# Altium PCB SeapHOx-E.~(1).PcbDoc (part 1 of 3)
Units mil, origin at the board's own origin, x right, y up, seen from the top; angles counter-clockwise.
Board outline 7300 x 3625 mil, 4 copper layers (Top Layer, Internal Plane 1, Signal Layer 1, Bottom Layer), stack 30.634 mil thick; 244 components, 217 nets, 966 pads, 416 vias.
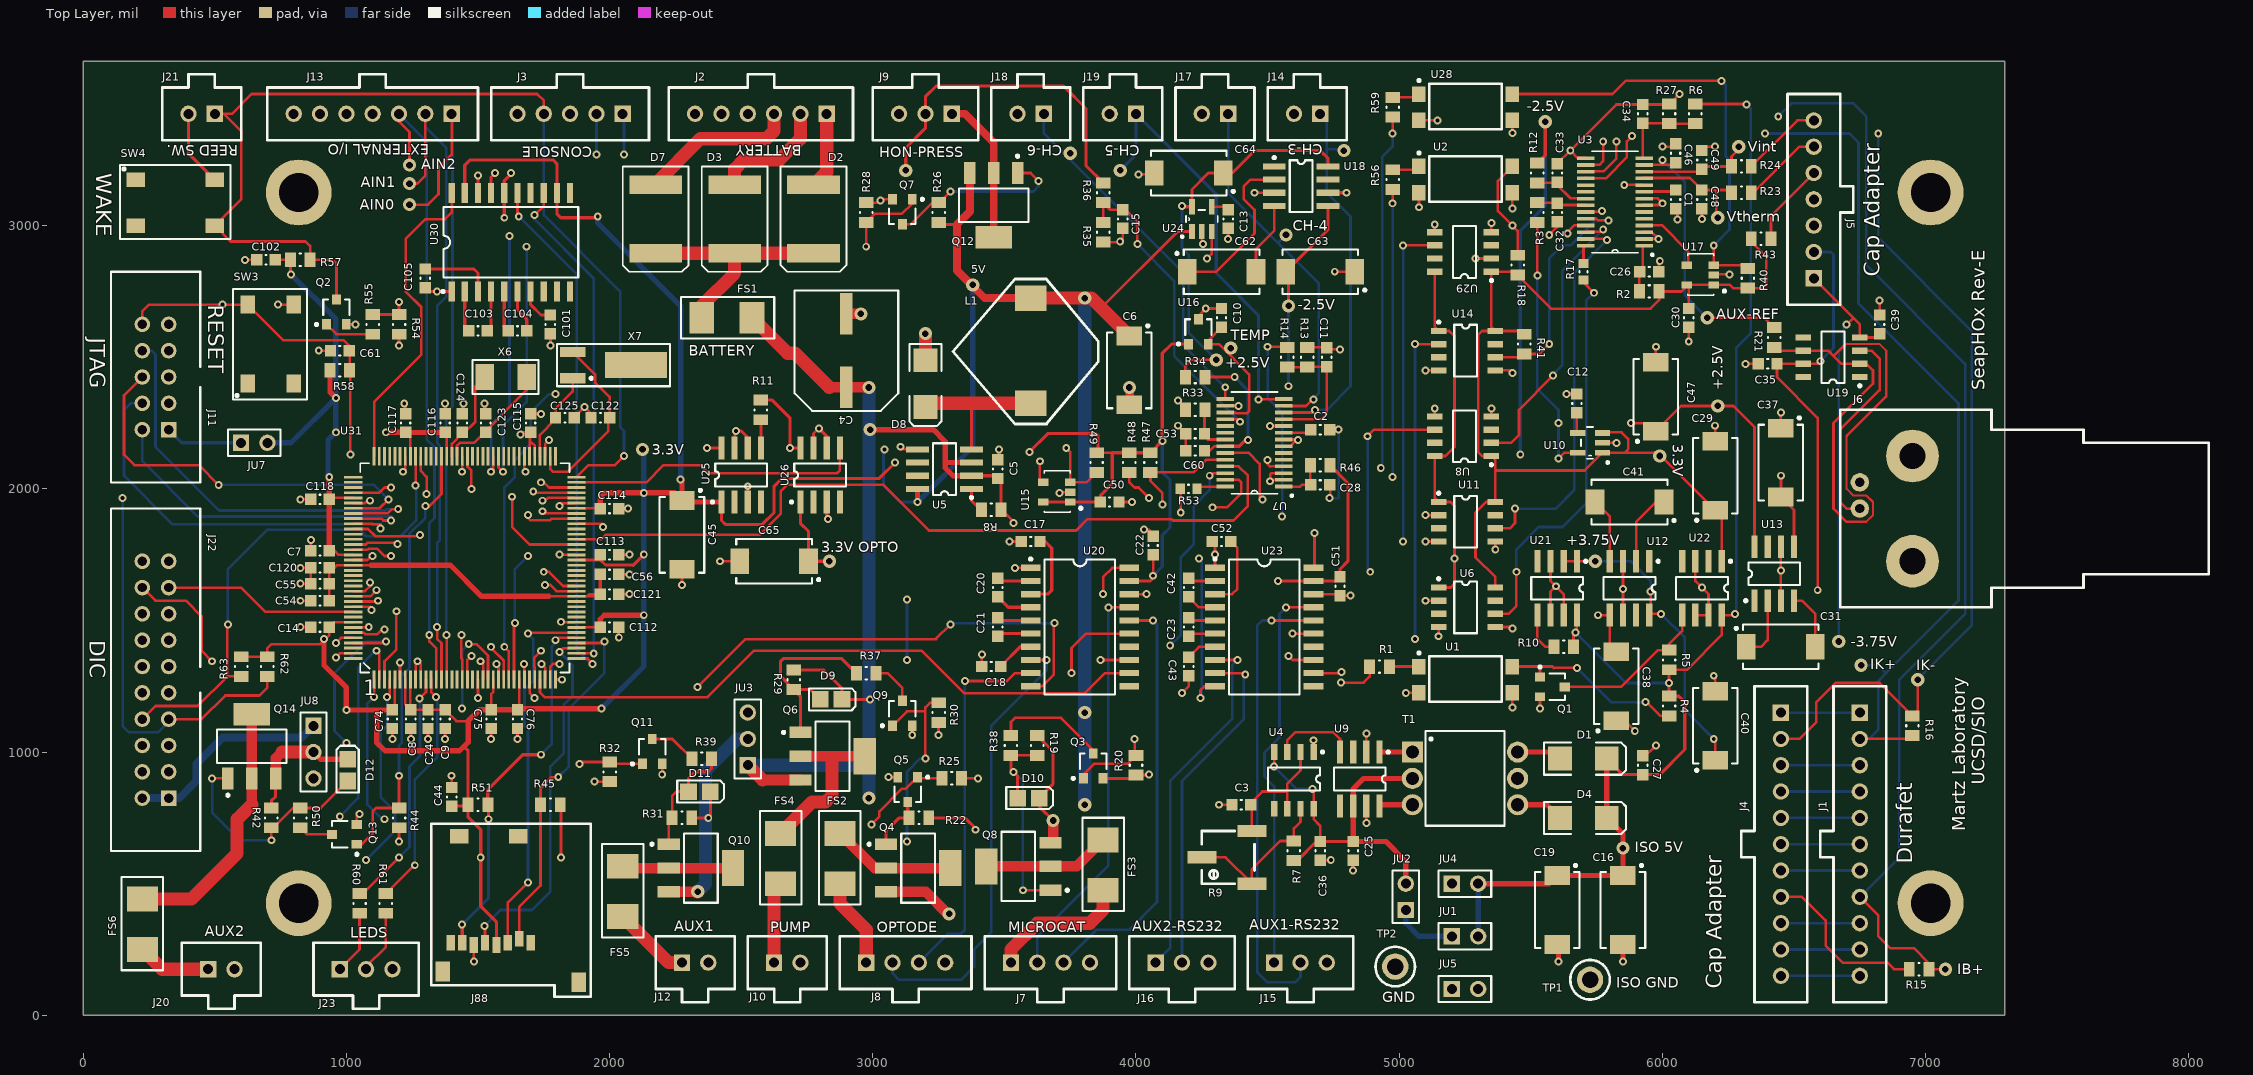
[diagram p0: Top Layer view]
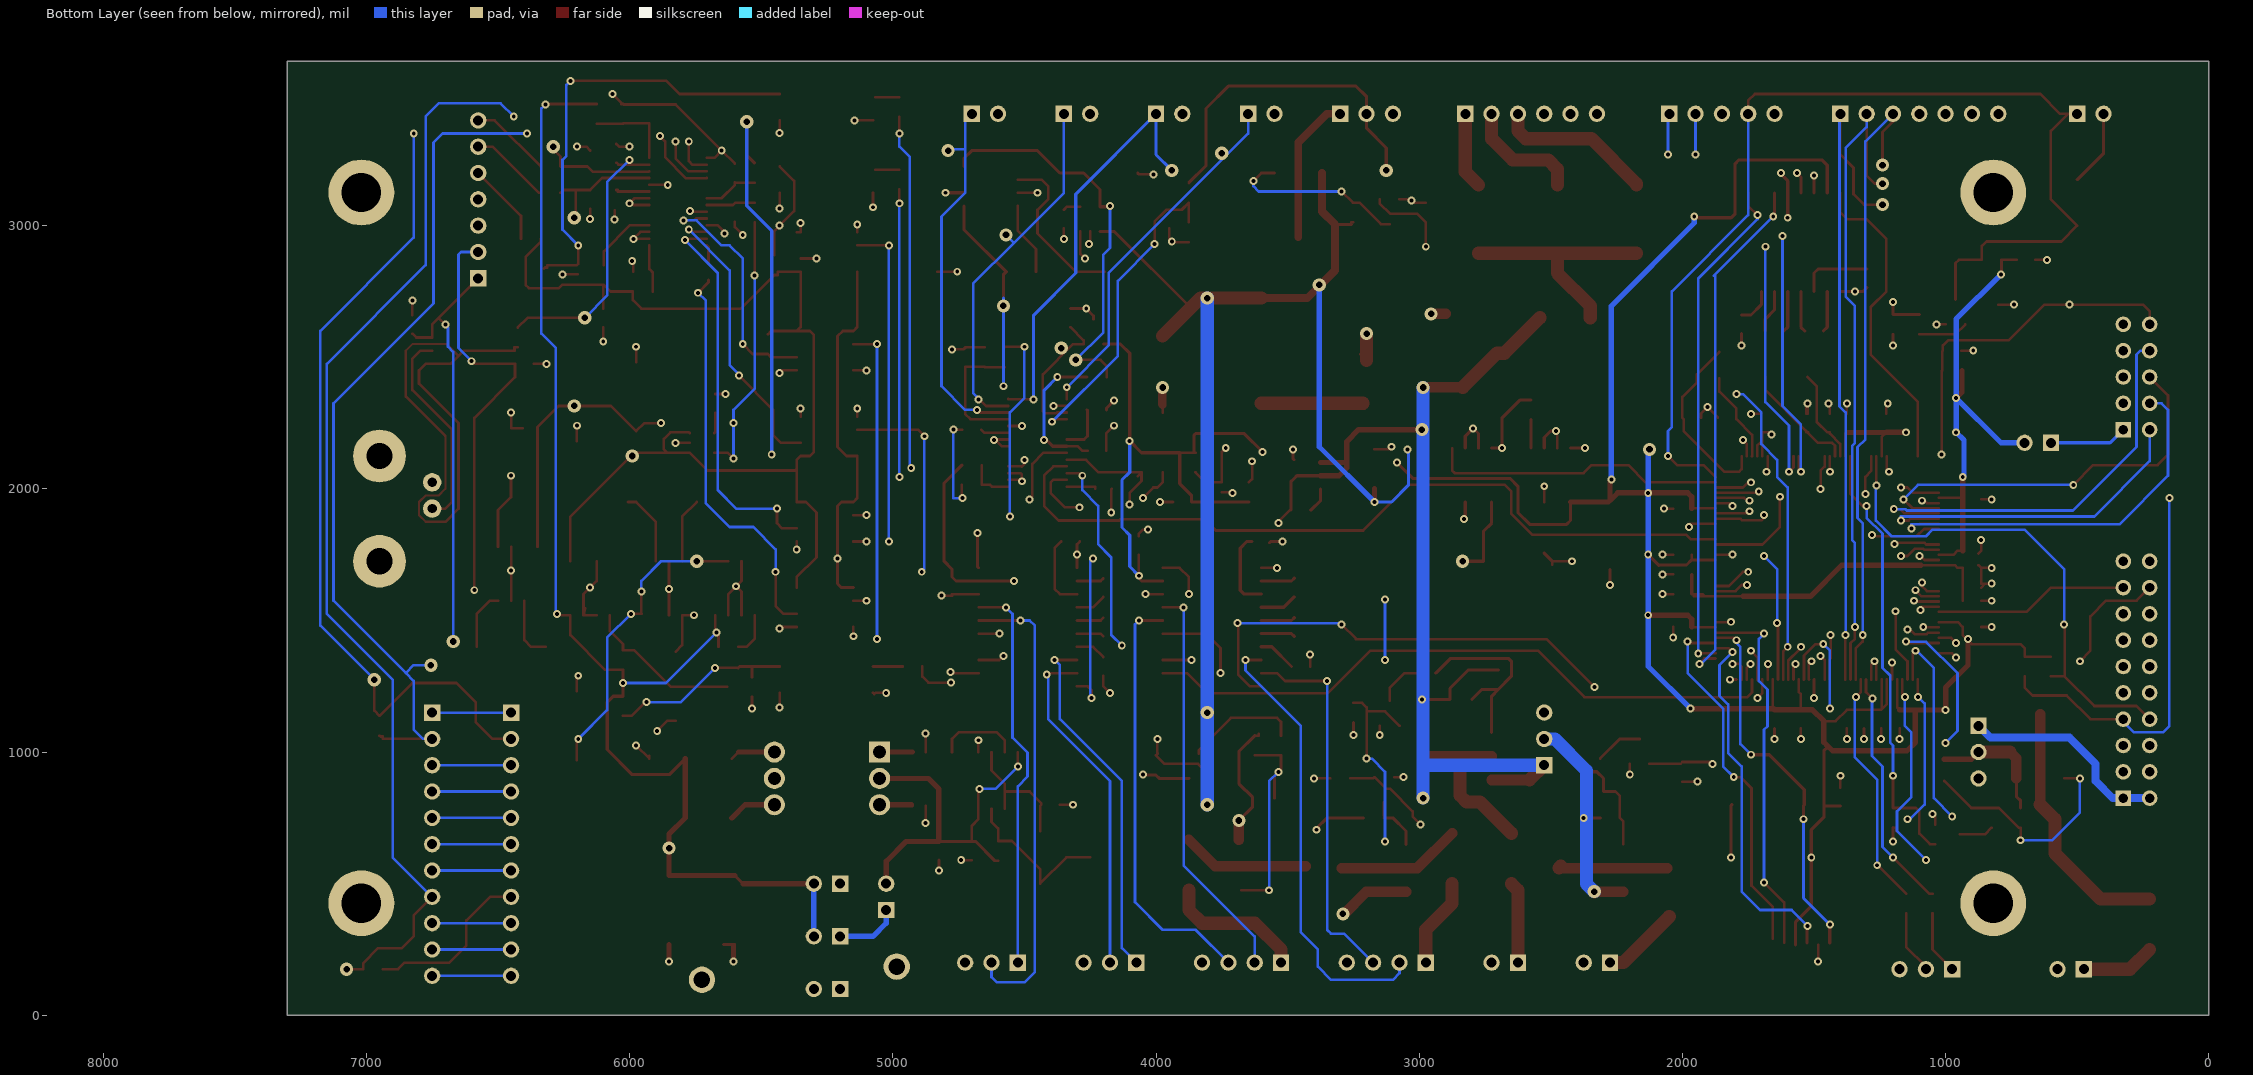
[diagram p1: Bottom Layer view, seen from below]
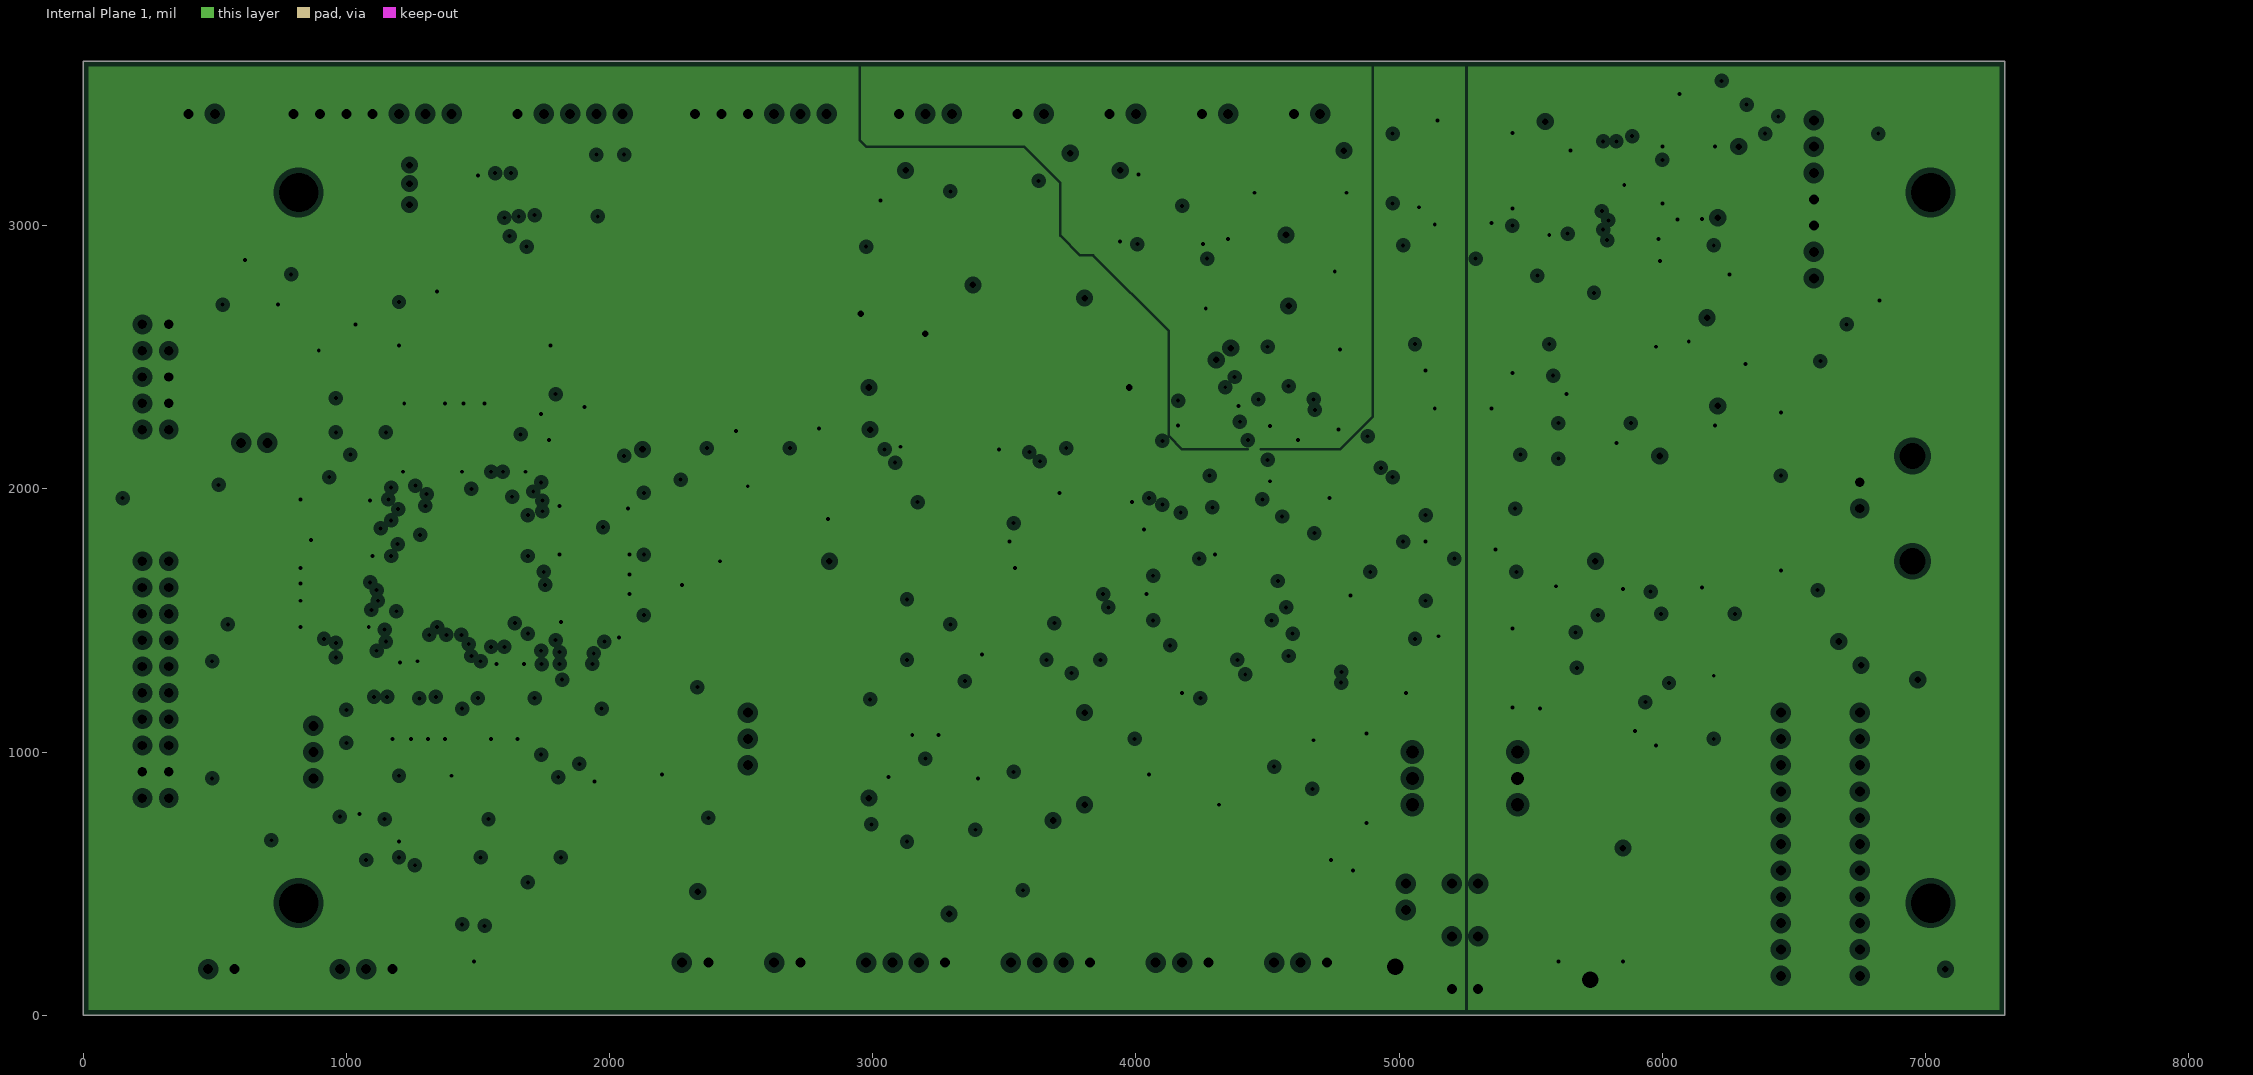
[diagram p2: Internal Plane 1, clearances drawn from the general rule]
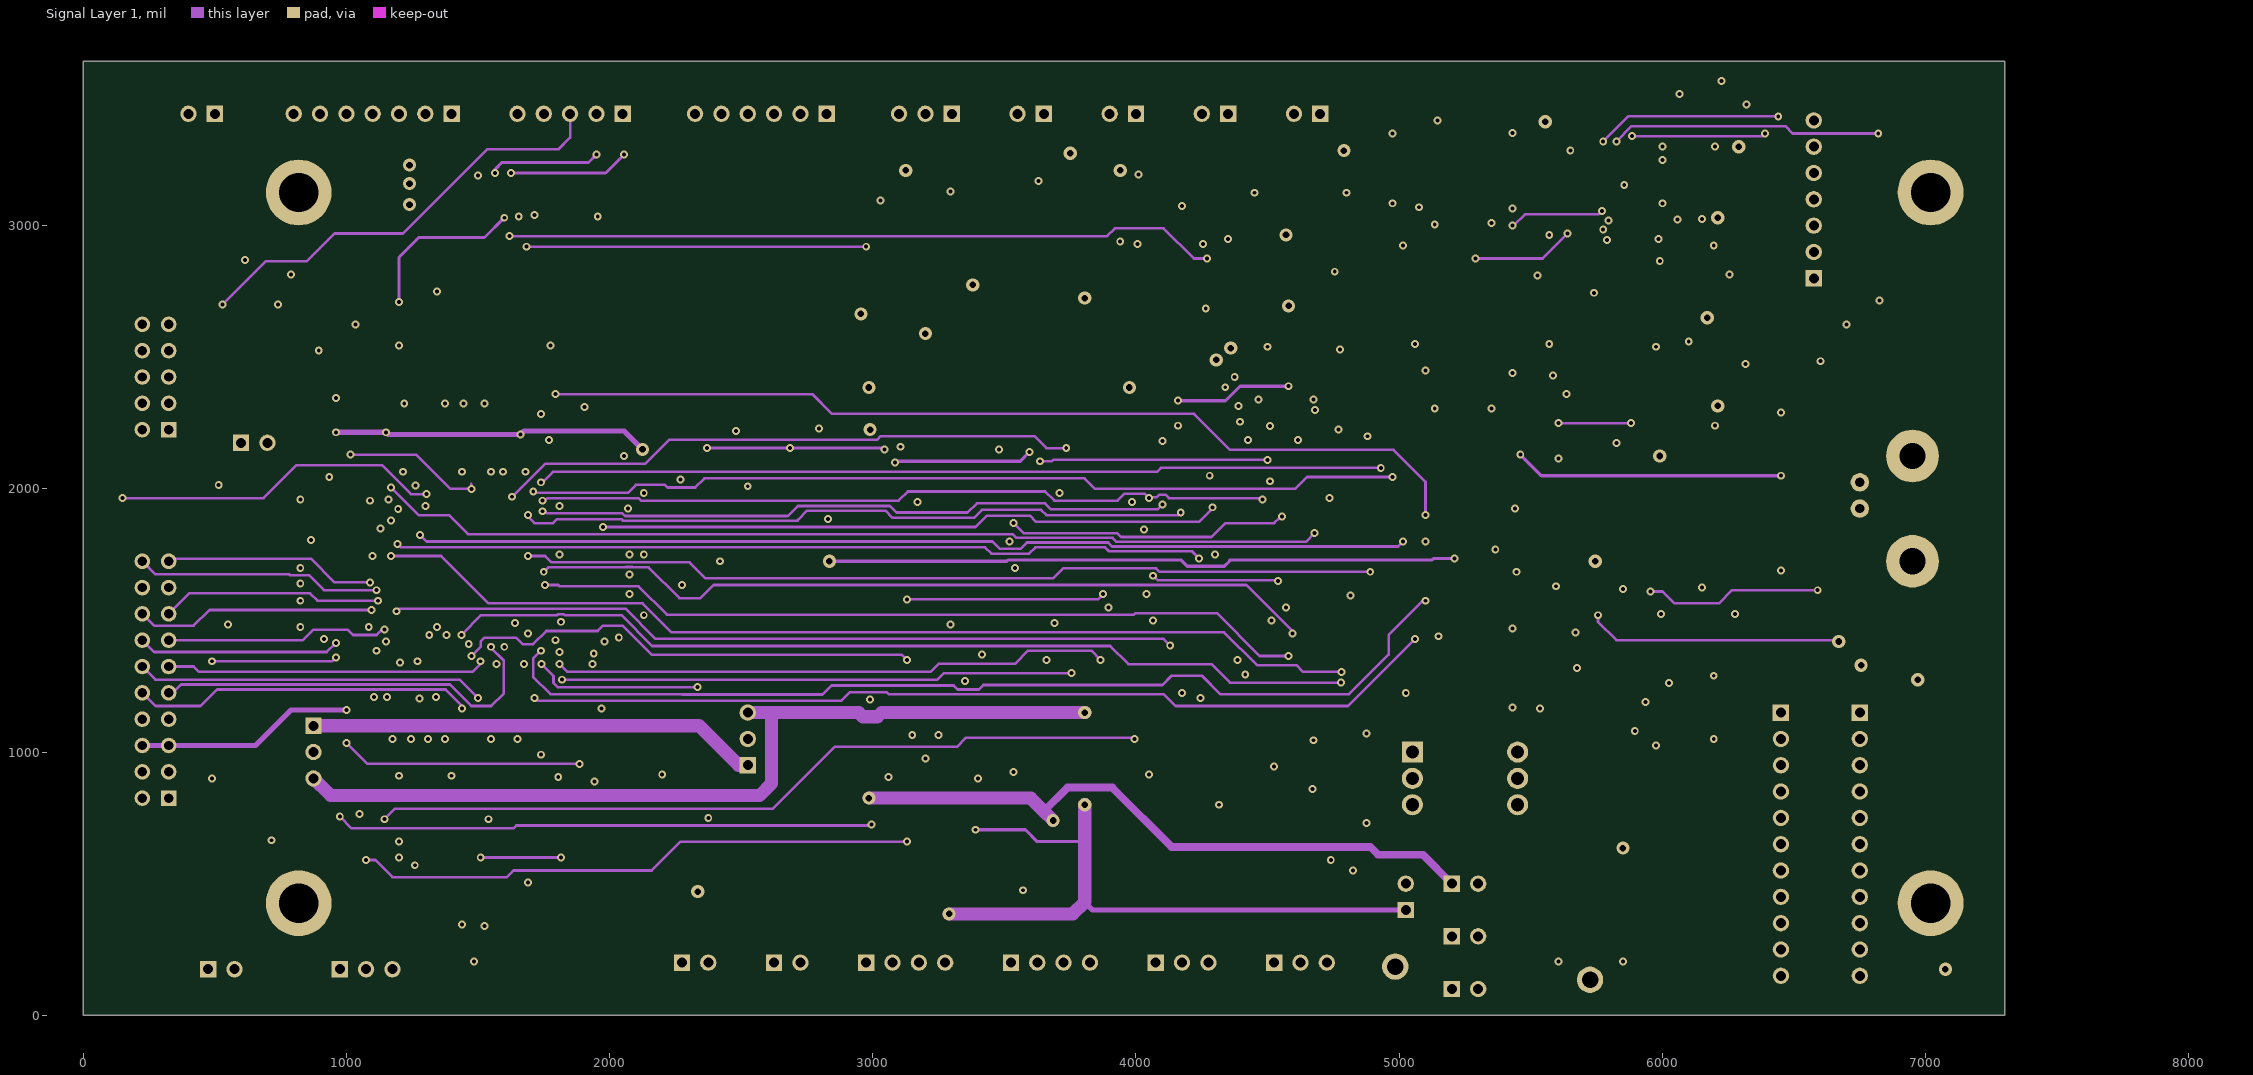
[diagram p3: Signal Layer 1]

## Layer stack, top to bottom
Top Solder: solder mask 0.4, Solder Resist, Dk 3.5
Top Layer: signal copper 1.4
Dielectric 1: core 10, FR-4, Dk 4.2
Internal Plane 1: plane copper 1.417, net (Multiple Nets)
Dielectric 3: prepreg 5, Dk 4.2
Signal Layer 1: signal copper 1.417
Dielectric 2: core 10, Dk 4.2
Bottom Layer: signal copper 1.4
Bottom Solder: solder mask 0.4, Solder Resist, Dk 3.5

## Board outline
0,0 0,3625 7300,3625 7300,0

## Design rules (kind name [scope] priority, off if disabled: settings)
AssemblyTestPointUsage [All] p0: scope1count=1 scope1_0_kind=Board scope1_0_value=Board scope2count=1 scope2_0_kind=Board scope2_0_value=Board commentlength=0
AssemblyTestpoint [All] p0: scope1count=1 scope1_0_kind=Board scope1_0_value=Board scope2count=1 scope2_0_kind=Board scope2_0_value=Board commentlength=0
Clearance [All] p0: scope1count=1 scope1_0_kind=Board scope1_0_value=Board scope2count=1 scope2_0_kind=Board scope2_0_value=Board commentlength=0 gap=8
Clearance [All] p1: gap=8
ComponentClearance [All] p0: scope1count=1 scope1_0_kind=Board scope1_0_value=Board scope2count=1 scope2_0_kind=Board scope2_0_value=Board commentlength=0 gap=6 collisioncheckmode=3
ComponentClearance [All] p1: gap=6 collisioncheckmode=3 verticalgap=10 showdistances=TRUE
DiffPairsRouting [All] p0: scope1count=1 scope1_0_kind=Board scope1_0_value=Board scope2count=1 scope2_0_kind=Board scope2_0_value=Board commentlength=0
FabricationTestPointUsage [All] p0: scope1count=1 scope1_0_kind=Board scope1_0_value=Board scope2count=1 scope2_0_kind=Board scope2_0_value=Board commentlength=0 valid=0 allowmultiple=FALSE
FabricationTestpoint [All] p0: scope1count=1 scope1_0_kind=Board scope1_0_value=Board scope2count=1 scope2_0_kind=Board scope2_0_value=Board commentlength=0 side=3 testpointundercomponent=TRUE minsize=40 maxsize=100 preferedsize=60 minholesize=0 maxholesize=40 preferedholesize=32 testpointgrid=1
FanoutControl Fanout_Default [All] p0: scope1count=1 scope1_0_kind=Board scope1_0_value=Board scope2count=1 scope2_0_kind=Board scope2_0_value=Board commentlength=30 // Fanout_Default (Default Rule)
FanoutControl Fanout_Small [All] p0 off: scope1count=1 scope1_0_kind=Board scope1_0_value=Board scope2count=1 scope2_0_kind=Board scope2_0_value=Board commentlength=84 // Protel DXP Scope 1 Expression Was: (CompPinCount < 5)   Fanout_Small (Default Rule)
FanoutControl Fanout_SOIC [All] p0 off: scope1count=1 scope1_0_kind=Board scope1_0_value=Board scope2count=1 scope2_0_kind=Board scope2_0_value=Board commentlength=71 // Protel DXP Scope 1 Expression Was: IsSOIC   Fanout_SOIC (Default Rule)
FanoutControl Fanout_LCC [All] p0 off: scope1count=1 scope1_0_kind=Board scope1_0_value=Board scope2count=1 scope2_0_kind=Board scope2_0_value=Board commentlength=69 // Protel DXP Scope 1 Expression Was: IsLCC   Fanout_LCC (Default Rule)
FanoutControl Fanout_BGA [All] p0 off: scope1count=1 scope1_0_kind=Board scope1_0_value=Board scope2count=1 scope2_0_kind=Board scope2_0_value=Board commentlength=69 // Protel DXP Scope 1 Expression Was: IsBGA   Fanout_BGA (Default Rule)
Height [All] p0: scope1count=1 scope1_0_kind=Board scope1_0_value=Board scope2count=1 scope2_0_kind=Board scope2_0_value=Board commentlength=0
HoleSize [All] p0: scope1count=1 scope1_0_kind=Board scope1_0_value=Board scope2count=1 scope2_0_kind=Board scope2_0_value=Board commentlength=0 absolutevalues=TRUE maxlimit=200 minlimit=15 maxpercent=80.000 minpercent=20.000
HoleSize [All] p1: absolutevalues=TRUE maxlimit=200 minlimit=15 maxpercent=80.000 minpercent=20.000
HoleToHoleClearance [All] p0: scope1count=1 scope1_0_kind=Board scope1_0_value=Board scope2count=1 scope2_0_kind=Board scope2_0_value=Board commentlength=0
LayerPairs [All] p0: scope1count=1 scope1_0_kind=Board scope1_0_value=Board scope2count=1 scope2_0_kind=Board scope2_0_value=Board commentlength=0 enforce=TRUE
MinimumSolderMaskSliver [All] p0 off: scope1count=1 scope1_0_kind=Board scope1_0_value=Board scope2count=1 scope2_0_kind=Board scope2_0_value=Board commentlength=0
MinimumSolderMaskSliver [All] p1 off: minsoldermaskwidth=5
NetAntennae [All] p0 off: scope1count=1 scope1_0_kind=Board scope1_0_value=Board scope2count=1 scope2_0_kind=Board scope2_0_value=Board commentlength=0
NetAntennae [All] p1 off: netantennaetolerance=0
PasteMaskExpansion [All] p0: scope1count=1 scope1_0_kind=Board scope1_0_value=Board scope2count=1 scope2_0_kind=Board scope2_0_value=Board commentlength=0 expansion=0
PlaneClearance [All] p0: scope1count=1 scope1_0_kind=Board scope1_0_value=Board scope2count=1 scope2_0_kind=Board scope2_0_value=Board commentlength=0 clearance=20
PlaneClearance [All] p1: clearance=20
PlaneConnect [All] p0: scope1count=1 scope1_0_kind=Board scope1_0_value=Board scope2count=1 scope2_0_kind=Board scope2_0_value=Board commentlength=0 planeconnectstyle=Relief reliefexpansion=20 reliefentries=4 reliefconductorwidth=10 reliefairgap=10
PlaneConnect [All] p1: planeconnectstyle=Relief reliefexpansion=20 reliefentries=4 reliefconductorwidth=10 reliefairgap=10
PolygonConnect [All] p0: scope1count=1 scope1_0_kind=Board scope1_0_value=Board scope2count=1 scope2_0_kind=Board scope2_0_value=Board commentlength=0 connectstyle=Relief reliefconductorwidth=10 reliefentries=4 polygonreliefangle="90 Angle"
PolygonConnect [All] p1: connectstyle=Relief reliefconductorwidth=10 reliefentries=4 polygonreliefangle="90 Angle" airgapwidth=10
RoutingCorners [All] p0: scope1count=1 scope1_0_kind=Board scope1_0_value=Board scope2count=1 scope2_0_kind=Board scope2_0_value=Board commentlength=0 cornerstyle=45-Degree minsetback=100 maxsetback=100
RoutingLayers [All] p0: scope1count=1 scope1_0_kind=Board scope1_0_value=Board scope2count=1 scope2_0_kind=Board scope2_0_value=Board commentlength=0 top layer=Automatic mid layer 1=Automatic bottom layer=Automatic
RoutingPriority [All] p0: scope1count=1 scope1_0_kind=Board scope1_0_value=Board scope2count=1 scope2_0_kind=Board scope2_0_value=Board commentlength=0
RoutingTopology [All] p0: scope1count=1 scope1_0_kind=Board scope1_0_value=Board scope2count=1 scope2_0_kind=Board scope2_0_value=Board commentlength=0 topology=Shortest
RoutingVias [All] p0: scope1count=1 scope1_0_kind=Board scope1_0_value=Board scope2count=1 scope2_0_kind=Board scope2_0_value=Board commentlength=0 holewidth=15 width=30 viastyle="Through Hole" minholewidth=15 minwidth=30 maxholewidth=28 maxwidth=50
RoutingVias [All] p1: holewidth=15 width=30 viastyle="Through Hole" minholewidth=15 minwidth=30 maxholewidth=28 maxwidth=50
SMDNeckDown [All] p0: scope1count=1 scope1_0_kind=Board scope1_0_value=Board scope2count=1 scope2_0_kind=Board scope2_0_value=Board commentlength=0 percent=100.000
SMDNeckDown [All] p1: percent=100.000
ShortCircuit [All] p0: scope1count=1 scope1_0_kind=Board scope1_0_value=Board scope2count=1 scope2_0_kind=Board scope2_0_value=Board commentlength=0 allowed=FALSE
SilkToBoardRegionClearance [All] p0 off: scope1count=1 scope1_0_kind=Board scope1_0_value=Board scope2count=1 scope2_0_kind=Board scope2_0_value=Board commentlength=0
SilkToBoardRegionClearance [All] p1 off:
SilkToSilkClearance [All] p0: scope1count=1 scope1_0_kind=Board scope1_0_value=Board scope2count=1 scope2_0_kind=Board scope2_0_value=Board commentlength=0
SilkToSilkClearance [All] p1: silktosilkclearance=1
SilkToSolderMaskClearance [All] p0 off: scope1count=1 scope1_0_kind=Board scope1_0_value=Board scope2count=1 scope2_0_kind=Board scope2_0_value=Board commentlength=44 // Protel DXP Scope 1 Expression Was: IsPad
SilkToSolderMaskClearance [IsPad] p1: minsilkscreentomaskgap=3 clearancetoexposedcopper=TRUE
SolderMaskExpansion [All] p0: scope1count=1 scope1_0_kind=Board scope1_0_value=Board scope2count=1 scope2_0_kind=Board scope2_0_value=Board commentlength=0 expansion=4
SolderMaskExpansion [All] p1: expansion=4
UnRoutedNet [All] p0: scope1count=1 scope1_0_kind=Board scope1_0_value=Board scope2count=1 scope2_0_kind=Board scope2_0_value=Board commentlength=0
UnpouredPolygon [All] p0: scope1count=1 scope1_0_kind=Board scope1_0_value=Board scope2count=1 scope2_0_kind=Board scope2_0_value=Board commentlength=0
Width [All] p0: scope1count=1 scope1_0_kind=Board scope1_0_value=Board scope2count=1 scope2_0_kind=Board scope2_0_value=Board commentlength=0 maxlimit=100 minlimit=8 preferedwidth=10
Width [All] p1: maxlimit=100 minlimit=8 preferedwidth=10
21 further rules are at their usual default settings.

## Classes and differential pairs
component class "Cortex Power and Voltage Regulators-D": C4 C5 C6 C7 C8 C9 C13 C14 C24 C45 C54 C55 C56 C61 C62 C63 C64 C65 C74 C75 C76 C112 C113 C114 C115 C116 C117 C118 C120 C121 C122 C123 C124 C125 D2 D3 D7 D8 FS1 J2 J21 L1 Q2 R8 R11 R54 R55 R57 R58 SW3 SW4 TP2 U5 U18 U24 U25 U26 U31 X6 X7
component class "Cortex Signal-D": C44 J11 J13 J22 J23 J88 JU7 R45 R51 R60 R61 R62 R63
component class "Isolated Circuits-D": C1 C26 C30 C32 C33 C35 C39 C46 C48 C49 J1 J4 J5 J6 R1 R2 R3 R12 R15 R16 R17 R18 R21 R23 R24 R40 R41 R43 R56 R59 U1 U2 U3 U6 U8 U11 U14 U17 U19 U28 U29
component class "Isolated Power Circuits-D": C3 C12 C16 C19 C25 C27 C29 C31 C34 C36 C37 C38 C40 C41 C47 D1 D4 JU1 JU2 JU4 JU5 Q1 R4 R5 R6 R7 R9 R10 R27 T1 TP1 U4 U9 U10 U12 U13 U21 U22
component class "Main Non-Isolated ADC-D": C2 C10 C11 C15 C28 C50 C53 C60 J9 J14 J17 J18 J19 Q7 Q12 R13 R14 R26 R28 R33 R34 R35 R36 R46 R47 R48 R49 R53 U7 U15 U16
component class "Pump and Aux Ports": D9 D11 D12 FS4 FS5 FS6 J10 J12 J20 JU3 JU8 Q6 Q9 Q10 Q11 Q13 Q14 R29 R30 R31 R32 R37 R39 R42 R44 R50
component class "RS232 and Perif Sensors-D": C17 C18 C20 C21 C22 C23 C42 C43 C51 C52 C101 C102 C103 C104 C105 D10 FS2 FS3 J3 J7 J8 J15 J16 Q3 Q4 Q5 Q8 R19 R20 R22 R25 R38 U20 U23 U30

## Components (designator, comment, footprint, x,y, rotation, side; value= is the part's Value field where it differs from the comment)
C1 "C1608X5R1A106K080AC" CAPC0603(1608)100_M#1 6050,3100 r90 top
C2 "C1608X5R1A106K080AC" CAPC0603(1608)100_M#1 4700,2225 r180 top
C3 "0.01uF" CAPC0603(1608)100_M#1 4400,800 r180 top
C4 "EEE-1HA101UP" CAP-VS-HA 2900,2525 r270 top
C5 "0.1uF/50V" CAPC0603(1608)100_M#1 3475,2075 r270 top
C6 "T495D107K010ATE100" CAPMP7343X29N 3975,2450 r270 top
C7 "0.1uF/50V" CAPC0603(1608)100_M#1 900,1765 r180 top
C8 "0.01uF" CAPC0603(1608)100_M#1 1245,1125 r270 top
C9 "" CAPC0603(1608)100_M#1 1375,1125 r270 top
C10 "C1608X5R1H105K080AB" CAPC0603(1608)100_M#1 4325,2650 r90 top
C11 "0.1uF/50V" CAPC0603(1608)100_M#1 4725,2500 r270 top
C12 "0.1uF/50V" CAPC0603(1608)100_M#1 5675,2325 r270 top
C13 "0.1uF/50V" CAPC0603(1608)100_M#1 4350,3025 r90 top
C14 "0.1uF/50V" CAPC0603(1608)100_M#1 900,1475 r180 top
C15 "0.1uF/50V" CAPC0603(1608)100_M#1 3950,3025 r90 top
C16 "TR3D337M010C0100" CAPMP7343X29N 5850,400 r270 top
C17 "0.1uF/50V" CAPC0603(1608)100_M#1 3600,1800 r180 top
C18 "0.1uF/50V" CAPC0603(1608)100_M#1 3450,1325 r180 top
C19 "TR3D337M010C0100" CAPMP7343X29N 5600,400 r270 top
C20 "0.1uF/50V" CAPC0603(1608)100_M#1 3475,1625 r270 top
C21 "0.1uF/50V" CAPC0603(1608)100_M#1 3475,1475 r270 top
C22 "0.1uF/50V" CAPC0603(1608)100_M#1 4065,1785 r90 top
C23 "0.1uF/50V" CAPC0603(1608)100_M#1 4200,1475 r270 top
C24 "0.1uF/50V" CAPC0603(1608)100_M#2 1310,1125 r270 top
C25 "0.1uF/50V" CAPC0603(1608)100_M#1 4825,625 r270 top
C26 "0.1uF/50V" CAPC0603(1608)100_M#1 5950,2825 r0 top
C27 "0.1uF/50V" CAPC0603(1608)100_M#1 5925,950 r270 top
C28 "0.1uF/50V" CAPC0603(1608)100_M#1 4700,2015 r0 top
C29 "T495D107K010ATE100" CAPMP7343X29N 6200,2050 r90 top
C30 "0.1uF/50V" CAPC0603(1608)100_M#1 6100,2650 r90 top
C31 "T495D107K010ATE100" CAPMP7343X29N 6450,1400 r0 top
C32 "0.1uF/50V" CAPC0603(1608)100_M#1 5600,3050 r90 top
C33 "0.1uF/50V" CAPC0603(1608)100_M#1 5600,3200 r270 top
C34 "0.1uF/50V" CAPC0603(1608)100_M#1 5925,3425 r270 top
C35 "0.1uF/50V" CAPC0603(1608)100_M#1 6400,2475 r0 top
C36 "0.1uF/50V" CAPC0603(1608)100_M#1 4700,625 r90 top
C37 "T495D107K010ATE100" CAPMP7343X29N 6450,2100 r270 top
C38 "T495D107K010ATE100" CAPMP7343X29N 5825,1250 r90 top
C39 "0.1uF/50V" CAPC0603(1608)100_M#1 6825,2625 r270 top
C40 "T495D107K010ATE100" CAPMP7343X29N 6200,1100 r90 top
C41 "T495D107K010ATE100" CAPMP7343X29N 5875,1950 r180 top
C42 "0.1uF/50V" CAPC0603(1608)100_M#1 4200,1625 r270 top
C43 "0.1uF/50V" CAPC0603(1608)100_M#1 4200,1325 r270 top
C44 "0.1uF/50V" CAPC0603(1608)100_M#1 1400,830 r270 top
C45 "T495D107K010ATE100" CAPMP7343X29N 2275,1825 r270 top
C46 "0.1uF/50V" CAPC0603(1608)100_M#1 6050,3275 r270 top
C47 "T495D107K010ATE100" CAPMP7343X29N 5975,2350 r90 top
C48 "0.1uF/50V" CAPC0603(1608)100_M#1 6150,3100 r270 top
C49 "0.1uF/50V" CAPC0603(1608)100_M#1 6150,3250 r270 top
C50 "0.1uF/50V" CAPC0603(1608)100_M#1 3900,1950 r180 top
C51 "0.1uF/50V" CAPC0603(1608)100_M#1 4775,1630 r270 top
C52 "0.1uF/50V" CAPC0603(1608)100_M#1 4325,1800 r180 top
C53 "0.1uF/50V" CAPC0603(1608)100_M#1 4225,2210 r0 top
C54 "C1608X5R1H105K080AB" CAPC0603(1608)100_M#1 900,1575 r180 top
C55 "C1608X5R1H105K080AB" CAPC0603(1608)100_M#1 900,1640 r180 top
C56 "C1608X5R1H105K080AB" CAPC0603(1608)100_M#1 2000,1675 r0 top
C60 "0.1uF/50V" CAPC0603(1608)100_M#1 4225,2145 r0 top
C61 "0.1uF/50V" CAPC0603(1608)100_M#1 975,2525 r0 top
C62 "T495D107K010ATE100" CAPMP7343X29N 4325,2825 r0 top
C63 "T495D107K010ATE100" CAPMP7343X29N 4700,2825 r180 top
C64 "T495D107K010ATE100" CAPMP7343X29N 4200,3200 r180 top
C65 "T495D107K010ATE100" CAPMP7343X29N 2625,1725 r180 top
C74 "0.1uF/50V" CAPC0603(1608)100_M#1 1175,1125 r90 top
C75 "0.1uF/50V" CAPC0603(1608)100_M#1 1550,1125 r90 top
C76 "0.1uF/50V" CAPC0603(1608)100_M#1 1650,1125 r90 top
C101 "0.1uF/50V" CAPC0603(1608)100_M#1 1775,2625 r270 top
C102 "0.1uF/50V" CAPC0603(1608)100_M#1 695,2870 r180 top
C103 "0.1uF/50V" CAPC0603(1608)100_M#1 1500,2600 r0 top
C104 "0.1uF/50V" CAPC0603(1608)100_M#1 1650,2600 r0 top
C105 "0.1uF/50V" CAPC0603(1608)100_M#1 1300,2800 r270 top
C112 "C1608X5R1H105K080AB" CAPC0603(1608)100_M#1 2000,1475 r0 top
C113 "C1608X5R1H105K080AB" CAPC0603(1608)100_M#1 2000,1750 r0 top
C114 "0.1uF/50V" CAPC0603(1608)100_M#1 2000,1925 r180 top
C115 "0.1uF/50V" CAPC0603(1608)100_M#1 1700,2250 r90 top
C116 "0.1uF/50V" CAPC0603(1608)100_M#1 1375,2250 r90 top
C117 "0.1uF/50V" CAPC0603(1608)100_M#1 1225,2250 r90 top
C118 "0.1uF/50V" CAPC0603(1608)100_M#1 900,1960 r180 top
C120 "0.01uF" CAPC0603(1608)100_M#1 900,1700 r180 top
C121 "0.01uF" CAPC0603(1608)100_M#1 2000,1600 r0 top
C122 "C1608C0G1H220J080AA" CAPC0603(1608)100_M#1 1965,2270 r180 top
C123 "C1608C0G1H100D080AA" CAPC0603(1608)100_M#1 1530,2250 r90 top
C124 "C1608C0G1H100D080AA" CAPC0603(1608)100_M#1 1440,2250 r90 top
C125 "C1608C0G1H220J080AA" CAPC0603(1608)100_M#1 1830,2270 r0 top
D1 "10BQ030" DO214AA 5700,975 r0 top
D2 "30BQ040" DO-214AB 2775,3025 r270 top
D3 "30BQ040" DO-214AB 2475,3025 r270 top
D4 "10BQ030" DO214AA 5700,750 r0 top
D7 "30BQ040" DO-214AB 2175,3025 r270 top
D8 "VS-10BQ100TRPBF" DO-214AA 3200,2400 r270 top
D9 "12V" "SOD323F 1005" 2800,1200 r0 top
D10 "" "SOD323F 1005" 3550,825 r0 top
D11 "12V" "SOD323F 1005" 2300,850 r0 top
D12 "12V" "SOD323F 1005" 1005,890 r90 top
FS1 "5A" FUSE-NANO-SMD 2350,2650 r0 top
FS2 "5A" FUSE-NANO-SMD 2875,500 r90 top
FS3 "5A" FUSE-NANO-SMD 3875,475 r90 top
FS4 "5A" FUSE-NANO-SMD 2650,500 r90 top
FS5 "5A" FUSE-NANO-SMD 2050,375 r90 top
FS6 "5A" FUSE-NANO-SMD 225,250 r90 top
J1 "0705430010" 70543-0010 6750,1150 r90 top
J2 "0705430005" 70543-0005 2825,3425 r0 top
J3 "0705430004" 70543-0004 2050,3425 r0 top
J4 "0705430010" 70543-0010 6450,1150 r90 top
J5 "0705430006" 70543-0006 6575,2800 r270 top
J6 "5226990-1" ? 6750,1925 r270 top
J7 "0705430003" 70543-0003 3525,200 r180 top
J8 "0705430003" 70543-0003 2975,200 r180 top
J9 "0705430002" 70543-0002 3300,3425 r0 top
J10 "0705430001" 70543-0001 2625,200 r180 top
J11 "D2510-6002-AR" D2510-6002 325,2225 r90 top
J12 "0705430001" 70543-0001 2275,200 r180 top
J13 "0705430006" 70543-0006 1400,3425 r0 top
J14 "0705430001" 70543-0001 4700,3425 r0 top
J15 "0705430002" 70543-0002 4525,200 r180 top
J16 "0705430002" 70543-0002 4075,200 r180 top
J17 "0705430001" 70543-0001 4350,3425 r0 top
J18 "0705430001" 70543-0001 3650,3425 r0 top
J19 "0705430001" 70543-0001 4000,3425 r0 top
J20 "0705430001" 70543-0001 475,175 r180 top
J21 "0705430001" 70543-0001 500,3425 r0 top
J22 "D2520-6002-AR" D2520-6002 325,825 r90 top
J23 "0705430002" 70543-0002 975,175 r180 top
J88 "2908-05WB-MG" 2908-05 1700,275 r180 top
JU1 "68001-202HLF" "Jump-2 100mil" 5200,300 r0 top
JU2 "68001-202HLF" "Jump-2 100mil" 5025,400 r90 top
JU3 "68000-203HLF" "JUMP-3 100MIL" 2525,950 r90 top
JU4 "68001-202HLF" "Jump-2 100mil" 5200,500 r0 top
JU5 "68001-202HLF" "Jump-2 100mil" 5200,100 r0 top
JU7 "68001-202HLF" "Jump-2 100mil" 600,2175 r0 top
JU8 "68000-203HLF" "JUMP-3 100MIL" 875,1100 r270 top
L1 "ELL-ATV101M" ELLATV 3600,2325 r90 top
Q1 "VN10LFTA" SOT23-3 5535,1285 r270 top
Q2 "MMBT3904" SOT23-3 925,2625 r0 top
Q3 "VN10LFTA" SOT23-3 3800,900 r0 top
Q4 "IRFL9014" SOT-223 3050,650 r270 top
Q5 "VN10LFTA" SOT23-3 3170,905 r180 top
Q6 "IRFL9014" SOT-223 2725,1075 r270 top
Q7 "VN10LFTA" SOT23-3 3150,3100 r180 top
Q8 "IRFL9014" SOT-223 3675,475 r90 top
Q9 "VN10LFTA" SOT23-3 3075,1100 r0 top
Q10 "IRFL9014" SOT-223 2225,650 r270 top
Q11 "VN10LFTA" SOT23-3 2125,955 r0 top
Q12 "IRFL9014" SOT-223 3550,3200 r180 top
Q13 "VN10LFTA" SOT23-3 1040,650 r90 top
Q14 "IRFL9014" SOT-223 550,900 r0 top
R1 "ERJ-6GEYJ202V" RESC0805(2012)_N 4925,1325 r0 top
R2 "ERJ-6GEYJ100V" RESC0805(2012)_N 5950,2750 r0 top
R3 "ERJ-6GEYJ100V" RESC0805(2012)_N 5525,3050 r270 top
R4 "ERJ-6GEYJ104V" RESC0805(2012)_N 6025,1175 r270 top
R5 "ERJ-6GEYJ105V" RESC0805(2012)_N 6025,1350 r90 top
R6 "ERJ-6ENF1004V" RESC0805(2012)_N 6125,3425 r90 top
R7 "ERJ-6GEYJ105V" RESC0805(2012)_N 4600,625 r270 top
R8 "ERJ-6GEYJ221V" RESC0805(2012)_N 3450,1920 r180 top
R9 "3269W-1-105GLF" 3269W 4250,600 r90 top
R10 "ERJ-6GEYJ105V" RESC0805(2012)_N 5625,1400 r0 top
R11 "ERJ-6GEYJ105V" RESC0805(2012)_N 2575,2300 r90 top
R12 "ERJ-6GEYJ100V" RESC0805(2012)_N 5525,3200 r90 top
R13 "ERJ-6ENF1003V" RESC0805(2012)_N 4650,2500 r270 top
R14 "1.00M/1%" RESC0805(2012)_N 4575,2500 r90 top
R15 "ERJ-6GEYJ103V" RESC0805(2012)_N 6975,175 r0 top
R16 "ERJ-6GEYJ103V" RESC0805(2012)_N 6950,1100 r270 top
R17 "ERJ-3GEYJ470V" RESC0603(1608)_N 5700,2825 r90 top
R18 "ERJ-6GEYJ104V" RESC0805(2012)_N 5450,2850 r270 top
R19 "ERJ-6GEYJ105V" RESC0805(2012)_N 3625,1025 r90 top
R20 "ERJ-6GEYJ105V" RESC0805(2012)_N 4000,950 r90 top
R21 "ERJ-6GEYJ103V" RESC0805(2012)_N 6425,2575 r90 top
R22 "ERJ-6GEYJ105V" RESC0805(2012)_N 3175,750 r0 top
R23 "ERJ-6GEYJ103V" RESC0805(2012)_N 6300,3125 r0 top
R24 "ERJ-6GEYJ103V" RESC0805(2012)_N 6300,3225 r0 top
R25 "ERJ-6GEYJ105V" RESC0805(2012)_N 3300,900 r180 top
R26 "ERJ-6GEYJ105V" RESC0805(2012)_N 3250,3050 r270 top
R27 "ERJ-6ENF1003V" RESC0805(2012)_N 6025,3425 r270 top
R28 "ERJ-6GEYJ105V" RESC0805(2012)_N 2975,3050 r270 top
R29 "ERJ-6GEYJ105V" RESC0805(2012)_N 2700,1275 r90 top
R30 "ERJ-6GEYJ105V" RESC0805(2012)_N 3250,1150 r90 top
R31 "ERJ-6GEYJ105V" RESC0805(2012)_N 2275,750 r0 top
R32 "ERJ-6GEYJ105V" RESC0805(2012)_N 2000,925 r90 top
R33 "ERJ-6GEYJ100V" RESC0805(2012)_N 4225,2300 r180 top
R34 "ERJ-6GEYJ100V" RESC0805(2012)_N 4225,2425 r180 top
R35 "ERJ-6GEYJ104V" RESC0805(2012)_N 3875,2975 r270 top
R36 "ERJ-6GEYJ224V" RESC0805(2012)_N 3875,3125 r270 top
R37 "ERJ-6GEYJ104V" RESC0805(2012)_N 2975,1300 r180 top
R38 "ERJ-6GEYJ104V" RESC0805(2012)_N 3525,1025 r270 top
R39 "ERJ-6GEYJ104V" RESC0805(2012)_N 2350,975 r0 top
R40 "ERJ-6GEYJ104V" RESC0805(2012)_N 6325,2800 r270 top
R41 "ERJ-6GEYJ104V" RESC0805(2012)_N 5475,2550 r90 top
R42 "ERJ-6GEYJ105V" RESC0805(2012)_N 715,750 r90 top
R43 "ERJ-6ENF2002V" RESC0805(2012)_N 6375,2950 r0 top
R44 "ERJ-6GEYJ105V" RESC0805(2012)_N 1200,750 r90 top
R45 "ERJ-6GEYJ103V" RESC0805(2012)_N 1775,800 r0 top
R46 "ERJ-6GEYJ100V" RESC0805(2012)_N 4700,2090 r0 top
R47 "ERJ-6GEYJ104V" RESC0805(2012)_N 4055,2100 r90 top
R48 "ERJ-6GEYJ104V" RESC0805(2012)_N 3975,2100 r90 top
R49 "ERJ-6GEYJ104V" RESC0805(2012)_N 3850,2100 r90 top
R50 "ERJ-6GEYJ104V" RESC0805(2012)_N 825,750 r90 top
R51 "ERJ-6GEYJ103V" RESC0805(2012)_N 1500,800 r180 top
R53 "ERJ-3GEYJ470V" RESC0603(1608)_N 4200,2000 r0 top
R54 "ERJ-6GEYJ105V" RESC0805(2012)_N 1200,2625 r90 top
R55 "ERJ-6GEYJ104V" RESC0805(2012)_N 1100,2625 r90 top
R56 "ERJ-6GEYJ202V" RESC0805(2012)_N 4975,3175 r90 top
R57 "ERJ-6GEYJ224V" RESC0805(2012)_N 825,2870 r0 top
R58 "ERJ-6GEYJ103V" RESC0805(2012)_N 975,2450 r180 top
R59 "ERJ-6GEYJ202V" RESC0805(2012)_N 4975,3450 r90 top
R60 "ERJ-6GEYJ331V" RESC0805(2012)_N 1050,425 r90 top
R61 "ERJ-6GEYJ331V" RESC0805(2012)_N 1150,425 r90 top
R62 "ERJ-6GEYJ202V" RESC0805(2012)_N 700,1325 r90 top
R63 "ERJ-6GEYJ202V" RESC0805(2012)_N 600,1325 r90 top
SW3 "B3S-1000P" B3S-100X 625,2400 r180 top
SW4 "B3S-1000P" B3S-100X 200,3175 r90 top
T1 "78253/55VC" DIP6 5050,1000 r270 top
TP1 "GND" TEST-POINT-0.063 5725,135 r0 top
TP2 "GND" TEST-POINT-0.063 4985,185 r0 top
U1 "FOD8523SD" 4-SMD 5075,1325 r270 top
U2 "FOD8523SD" 4-SMD 5075,3225 r270 top
U3 "ADS1248" TSSOP28 5820,3090 r180 top
U4 "LMC555CMX" MS-012-AA 4675,1000 r180 top
U5 "LT1073CS8-5" SOIC8 3375,2000 r90 top
U6 "FOD8001" MS-012-AA 5150,1625 r270 top
U7 "ADS1248" TSSOP28 4450,2175 r180 top
U8 "FOD8001" MS-012-AA 5350,2125 r90 top
U9 "MAX253CSA" SOIC8 4925,1000 r180 top
U10 "TPS79225DBV" TI-DBV5 5725,2175 r180 top
U11 "FOD8001" MS-012-AA 5150,1950 r270 top
U12 "MAX660M" SOIC8 5950,1725 r180 top
U13 "MAX660M" SOIC8 6350,1575 r0 top
U14 "FOD8001" MS-012-AA 5150,2600 r270 top
U15 "TPS3836L30DBV" SOT23-5 3750,1950 r90 top
U16 "LM62BIM3" SOT23-3 4200,2550 r0 top
U17 "TPS3836L30DBV" SOT23-5 6195,2775 r90 top
U18 "MAX660M" SOIC8 4525,3225 r270 top
U19 "LMC6041AIM" MS-012-AA 6750,2425 r90 top
U20 "MAX3222CDW" SOIC20 3600,1700 r270 top
U21 "LT1121CS8" SOIC8 5675,1725 r180 top
U22 "LT1121CS8-3.3" SOIC8 6225,1725 r180 top
U23 "MAX3222CDW" SOIC20 4300,1700 r270 top
U24 "TPS79225DBV" TI-DBV5 4250,3025 r90 top
U25 "LT1121CS8-3.3" SOIC8 2425,1950 r0 top
U26 "LT1121CS8-3.3" SOIC8 2725,1950 r0 top
U28 "FOD8523SD" 4-SMD 5075,3500 r270 top
U29 "FOD8001" MS-012-AA 5350,2825 r90 top
U30 "MAX3222CDW" SOIC20 1400,2750 r0 top
U31 "TM4C123GH6PGEI" PGE144-M 1450,1700 r90 top
X6 "16.000 MHz" ABM3 1525,2425 r0 top
X7 "32.768 kHz" AB26TRB 1860,2420 r180 top

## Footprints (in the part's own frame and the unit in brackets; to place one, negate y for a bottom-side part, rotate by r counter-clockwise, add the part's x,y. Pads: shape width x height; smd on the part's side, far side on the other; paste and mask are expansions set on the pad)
4-SMD [mm] "4-pin surface mount"
  rect 1.5x1.3 smd: 1(0,0) 2(2.54,0) 3(2.54,9.017) 4(0,9.017)
  silkscreen extent -1.42,-0.12 3.4,8
2908-05 [mm] "3M microSD card connector"
  rect 1.4x1.9 smd: 0(-4.66,3.8) 0(8.49,2.75)
  rect 1.8x1.4 smd: 0(1.19,-10.3) 0(6.89,-10.3)
  rect 0.8x1.5 smd: 1(0,0) 2(1.1,-0.4) 3(2.2,0) 4(3.3,0.2) 5(4.4,0) 6(5.5,0.2) 7(6.6,0) 8(7.7,0)
  Top Layer keep-out lines w0.254: 9.6,1.5 9.6,-10.9
  silkscreen extent -5.8,-11.5 9.6,5.2
3269W [mil] "Bourns 3269W pot."
  rect 47x110 smd: 1(-100,-190) 2(0,0) 3(100,-190)
  silkscreen extent -100,-200 100,0
70543-0001 [mil] "CGRID Vert. Header, 2-pin,"
  rect 62x62 hole 38: 1(0,0)
  round 62 hole 38: 2(-100,0)
  silkscreen extent -200,-100 100,150
70543-0002 [mil] "CGRID Vert Header, 3-pin"
  rect 62x62 hole 38: 1(0,0)
  round 62 hole 38: 2(-100,0) 3(-200,0)
  silkscreen extent -300,-100 100,150
70543-0003 [mil] "CGRID Vert Header, 4-pin"
  rect 62x62 hole 38: 1(0,0)
  round 62 hole 38: 2(-100,0) 3(-200,0) 4(-300,0)
  silkscreen extent -400,-100 100,150
70543-0004 [mil] "CGRID Vert Header, 5-pin"
  rect 62x62 hole 38: 1(0,0)
  round 62 hole 38: 2(-100,0) 3(-200,0) 4(-300,0) 5(-400,0)
  silkscreen extent -500,-100 100,150
70543-0005 [mil] "CGRID Vert Header, 6-pin"
  rect 62x62 hole 38: 1(0,0)
  round 62 hole 38: 2(-100,0) 3(-200,0) 4(-300,0) 5(-400,0) 6(-500,0)
  silkscreen extent -600,-100 100,150
70543-0006 [mil] "CGRID Vert Header, 7-pin"
  rect 62x62 hole 38: 1(0,0)
  round 62 hole 38: 2(-100,0) 3(-200,0) 4(-300,0) 5(-400,0) 6(-500,0) 7(-600,0)
  silkscreen extent -700,-100 100,150
70543-0010 [mil] "CGRID Vert Header, 11-pin"
  rect 62x62 hole 38: 1(0,0)
  round 62 hole 38: 2(-100,0) 3(-200,0) 4(-300,0) 5(-400,0) 6(-500,0) 7(-600,0) 8(-700,0) 9(-800,0) 10(-900,0) 11(-1000,0)
  silkscreen extent -1100,-100 100,150
AB26TRB [mm]
  rect 2.5x1 smd: 1(0,0) 3(0,-2.54)
  rect 6x2.5 smd: 2(-6.096,-1.27)
  silkscreen extent -9.4,-3.3 1.52,0.76
ABM3 [mil] "Abracon miniature ceramic SMD crystal 5.0 x 3.2 x 1.3 mm"
  rect 70x100 smd: 1(0,0) 2(160,0)
  silkscreen extent -45,-65 205,65
B3S-100X [mm] "Switch, Omron B3S series, no ground"
  rect 1.4x1.75 smd: 1(0,0) 2(0,-7.62) 3(-4.445,0) 4(-4.445,-7.62)
  silkscreen extent -5.72,-9.14 1.4,1.52
CAP-VS-HA [mm]
  rect 4x1.2 smd: 1(3.55,0) 2(-3.55,0)
  silkscreen extent -5.8,-5 5.8,5
CAPC0603(1608)100_M#1 [mm] "Chip Capacitor, Body 1.6x0.8mm, Height 1.0mm, IPC Low Density"
  rect 1.1x1.1 smd: 1(-0.9,0) 2(0.9,0)
  silkscreen extent -0.05,-0.45 0.05,0.45
CAPC0603(1608)100_M#2 [mm] "Chip Capacitor, Body 1.6x0.8mm, Height 1.0mm, IPC Low Density"
  rect 1.1x1.1 smd: 1(-0.9,0) 2(0.9,0)
  Mechanical 13 keep-out region: 17.406,114.825 17.406,115.807 13.106,115.807 13.106,114.825
  silkscreen extent -0.05,-0.45 0.05,0.45
CAPMP7343X29N [mm] "Molded Capacitor, 2-Leads, Body 7.30x4.30mm, IPC Medium Density"
  rect 1.8x2.45 smd: 1(-3.325,0) 2(3.325,0)
  silkscreen extent -4.42,-2.15 3.65,2.15
D2510-6002 [mm] "3M 10-pos vertical header"
  rect 1.5x1.5 hole 0.9: 1(0,0)
  round 1.5 hole 0.9: 2(0,2.54) 3(2.54,0) 4(2.54,2.54) 5(5.08,0) 6(5.08,2.54) 7(7.62,0) 8(7.62,2.54) 9(10.16,0) 10(10.16,2.54)
  silkscreen extent -5.08,-3.05 15.24,5.59
D2520-6002 [mm] "3M 20-pos vertical header"
  rect 1.5x1.5 hole 0.9: 1(0,0)
  round 1.5 hole 0.9: 2(0,2.54) 3(2.54,0) 4(2.54,2.54) 5(5.08,0) 6(5.08,2.54) 7(7.62,0) 8(7.62,2.54) 9(10.16,0) 10(10.16,2.54) 11(12.7,0) 12(12.7,2.54) 13(15.24,0) 14(15.24,2.54) 15(17.78,0) 16(17.78,2.54) 17(20.32,0) 18(20.32,2.54) 19(22.86,0) 20(22.86,2.54)
  silkscreen extent -5.08,-3.05 27.94,5.59
DIP6 [mil]
  rect 80x80 hole 50: 1(0,0)
  round 80 hole 50: 2(100,0) 3(200,0) 4(200,400) 5(100,400) 6(0,400)
  silkscreen extent -80,50 280,350
DO214AA [mm] "DO-214-AA/SMB; 2 C-Bend Leads; Body 5.3 x 3.6 mm, inc. leads (LxW)"
  rect 2.3x2.3 smd: 1(-2.25,0) 2(2.25,0)
  silkscreen extent -3.8,-1.55 4.1,1.55
DO-214AA [mm] "DO-214-AA/SMB; 2 C-Bend Leads; Body 5.3 x 3.6 mm, inc. leads (LxW)"
  rect 2.3x2.3 smd: 1(-2.25,0) 2(2.25,0)
  silkscreen extent -3.8,-1.55 4.1,1.55
DO-214AB [mil] "Diode, surface mount"
  rect 70x200 smd: 1(-130,0) 2(130,0)
  silkscreen extent -200,-125 200,125
ELLATV [mm] "Panasonic ELLATV SMD Choke Coil"
  rect 2.45x3 smd: 1(0,0) 2(10.15,0)
  silkscreen extent -2,-6.5 12,7.5
FUSE-NANO-SMD [mm] "FUSE NANO SMD"
  rect 2.4x3 smd: 1(0,0) 2(4.86,0)
  silkscreen extent -2,-2 7,2
"Jump-2 100mil" [mil] "Jumper, 2-pin"
  rect 62x62 hole 38: 1(0,0)
  round 62 hole 38: 2(100,0)
  silkscreen extent -50,-50 150,50
"JUMP-3 100MIL" [mil]
  rect 62x62 hole 38: 1(0,0)
  round 62 hole 38: 2(100,0) 3(200,0)
  silkscreen extent -50,-50 250,50
MS-012-AA [mil] "8 lead small outline"
  rect 24x60 smd: 1(0,0) 2(50,0) 3(100,0) 4(150,0) 5(150,215) 6(100,215) 7(50,215) 8(0,215)
  silkscreen extent -38,-5 173,146
PGE144-M [mm]
  rect 1.766x0.27 smd: 1(-10.776,8.75) 2(-10.776,8.25) 3(-10.776,7.75) 4(-10.776,7.25) 5(-10.776,6.75) 6(-10.776,6.25) 7(-10.776,5.75) 8(-10.776,5.25) 9(-10.776,4.75) 10(-10.776,4.25) 11(-10.776,3.75) 12(-10.776,3.25) 13(-10.776,2.75) 14(-10.776,2.25) 15(-10.776,1.75) 16(-10.776,1.25) 17(-10.776,0.75) 18(-10.776,0.25) 19(-10.776,-0.25) 20(-10.776,-0.75) 21(-10.776,-1.25) 22(-10.776,-1.75) 23(-10.776,-2.25) 24(-10.776,-2.75) 25(-10.776,-3.25) 26(-10.776,-3.75) 27(-10.776,-4.25) 28(-10.776,-4.75) 29(-10.776,-5.25) 30(-10.776,-5.75) 31(-10.776,-6.25) 32(-10.776,-6.75) 33(-10.776,-7.25) 34(-10.776,-7.75) 35(-10.776,-8.25) 36(-10.776,-8.75) 73(10.776,-8.75) 74(10.776,-8.25) 75(10.776,-7.75) 76(10.776,-7.25) 77(10.776,-6.75) 78(10.776,-6.25) 79(10.776,-5.75) 80(10.776,-5.25) 81(10.776,-4.75) 82(10.776,-4.25) 83(10.776,-3.75) 84(10.776,-3.25) 85(10.776,-2.75) 86(10.776,-2.25) 87(10.776,-1.75) 88(10.776,-1.25) 89(10.776,-0.75) 90(10.776,-0.25) 91(10.776,0.25) 92(10.776,0.75) 93(10.776,1.25) 94(10.776,1.75) 95(10.776,2.25) 96(10.776,2.75) 97(10.776,3.25) 98(10.776,3.75) 99(10.776,4.25) 100(10.776,4.75) 101(10.776,5.25) 102(10.776,5.75) 103(10.776,6.25) 104(10.776,6.75) 105(10.776,7.25) 106(10.776,7.75) 107(10.776,8.25) 108(10.776,8.75)
  rect 0.27x1.766 smd: 37(-8.75,-10.776) 38(-8.25,-10.776) 39(-7.75,-10.776) 40(-7.25,-10.776) 41(-6.75,-10.776) 42(-6.25,-10.776) 43(-5.75,-10.776) 44(-5.25,-10.776) 45(-4.75,-10.776) 46(-4.25,-10.776) 47(-3.75,-10.776) 48(-3.25,-10.776) 49(-2.75,-10.776) 50(-2.25,-10.776) 51(-1.75,-10.776) 52(-1.25,-10.776) 53(-0.75,-10.776) 54(-0.25,-10.776) 55(0.25,-10.776) 56(0.75,-10.776) 57(1.25,-10.776) 58(1.75,-10.776) 59(2.25,-10.776) 60(2.75,-10.776) 61(3.25,-10.776) 62(3.75,-10.776) 63(4.25,-10.776) 64(4.75,-10.776) 65(5.25,-10.776) 66(5.75,-10.776) 67(6.25,-10.776) 68(6.75,-10.776) 69(7.25,-10.776) 70(7.75,-10.776) 71(8.25,-10.776) 72(8.75,-10.776) 109(8.75,10.776) 110(8.25,10.776) 111(7.75,10.776) 112(7.25,10.776) 113(6.75,10.776) 114(6.25,10.776) 115(5.75,10.776) 116(5.25,10.776) 117(4.75,10.776) 118(4.25,10.776) 119(3.75,10.776) 120(3.25,10.776) 121(2.75,10.776) 122(2.25,10.776) 123(1.75,10.776) 124(1.25,10.776) 125(0.75,10.776) 126(0.25,10.776) 127(-0.25,10.776) 128(-0.75,10.776) 129(-1.25,10.776) 130(-1.75,10.776) 131(-2.25,10.776) 132(-2.75,10.776) 133(-3.25,10.776) 134(-3.75,10.776) 135(-4.25,10.776) 136(-4.75,10.776) 137(-5.25,10.776) 138(-5.75,10.776) 139(-6.25,10.776) 140(-6.75,10.776) 141(-7.25,10.776) 142(-7.75,10.776) 143(-8.25,10.776) 144(-8.75,10.776)
  silkscreen extent -10.1,-10.1 10.1,10.1
RESC0603(1608)_N [mm] "Chip Resistor, Body 1.6x0.8mm, IPC Medium Density"
  rect 0.9x1 smd: 1(-0.8,0) 2(0.8,0)
  silkscreen extent -0.05,-0.4 0.05,0.4
RESC0805(2012)_N [mm] "Chip Resistor, Body 2.0x1.3mm, IPC Medium Density"
  rect 1.05x1.4 smd: 1(-0.95,0) 2(0.95,0)
  silkscreen extent -0.05,-0.6 0.05,0.6
"SOD323F 1005" [mil]
  rect 63x63 smd: 1(0,0) 2(83,0)
  silkscreen extent -43,-42 134,42
SOIC8 [mm]
  rect 0.6x2.2 smd: 1(0,0) 2(1.27,0) 3(2.54,0) 4(3.81,0) 5(3.81,5.2) 6(2.54,5.2) 7(1.27,5.2) 8(0,5.2)
  silkscreen extent -0.97,-0.12 4.4,3.7
SOIC20 [mm] "Small Outline; 20 Leads; Body Width 7.5 mm; Pitch 1.27 mm"
  rect 0.6x1.9 smd: 1(0,0) 2(1.27,0) 3(2.54,0) 4(3.81,0) 5(5.08,0) 6(6.35,0) 7(7.62,0) 8(8.89,0) 9(10.16,0) 10(11.43,0) 11(11.43,9.5) 12(10.16,9.5) 13(8.89,9.5) 14(7.62,9.5) 15(6.35,9.5) 16(5.08,9.5) 17(3.81,9.5) 18(2.54,9.5) 19(1.27,9.5) 20(0,9.5)
  silkscreen extent -0.97,-0.12 12.21,8.15
SOT23-3 [mm] "SOT-23; 3 Leads; Body 3.0 x 2.5 mm, inc. leads (LxW max)"
  rect 0.85x1 smd: 1(0,0) 2(1.9,0) 3(0.95,2.4)
  silkscreen extent -1.1,-0.12 2.23,2.4
SOT23-5 [mm] "SOT-23; 5 Leads; Body 3 x 1.7 mm"
  rect 0.7x1 smd: 1(0,0) 2(0.95,0) 3(1.9,0) 4(1.9,2.6) 5(0,2.6)
  silkscreen extent -1,-1.15 3,2.5
SOT-223 [mm] "SOT-223/SC-73; 4 Leads; Body 6.7 x 7.3 mm, inc. leads (LxW max)"
  rect 1.1x2.15 smd: 1(0,0) 2(2.3,0) 3(4.6,0)
  rect 3.5x2.15 smd: 4(2.3,6.2)
  silkscreen extent -1.05,-1.75 5.65,4.73
TEST-POINT-0.063 [mil] "Test point, 0.063"
  round 100 hole 63: 1(0,0)
  silkscreen extent -75,-75 75,75
TI-DBV5 [mil]
  rect 58x22 smd: 1(-47,37.4) 2(-47,0) 3(-47,-37.4) 4(47,-37.4) 5(47,37.4)
  silkscreen extent -71,-60 34,79
TSSOP28 [mil] "28-pin plastic small outline, JEDEC MO-153"
  rect 66x14 smd: 1(-111,166.34) 2(-111,140.75) 3(-111,115.16) 4(-111,89.57) 5(-111,63.98) 6(-111,38.39) 7(-111,12.8) 8(-111,-12.8) 9(-111,-38.39) 10(-111,-63.98) 11(-111,-89.57) 12(-111,-115.16) 13(-111,-140.75) 14(-111,-166.34) 15(111,-166.34) 16(111,-140.75) 17(111,-115.16) 18(111,-89.57) 19(111,-63.98) 20(111,-38.39) 21(111,-12.8) 22(111,12.8) 23(111,38.39) 24(111,63.98) 25(111,89.57) 26(111,115.16) 27(111,140.75) 28(111,166.34)
  silkscreen extent -146,-193 89,205
? [mil] "BNC Jack, right angle"
  round 200 hole 100: 0(-200,200) 0(200,200)
  round 70 hole 35: 1(0,0) 2(-100,0)
  silkscreen extent -375,-75 375,1326

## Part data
C1 C2: "CAP CER 10UF 10V 10% X5R 0603"
C3 C8 C120 C121: library part C1608X7R1H103K080AA, "CAP CER 10000PF 50V 10% X7R 0603"
C4: "CAP ALUM 100UF 50V 20% SMD"
C5 C7 C11 C12 C13 C14 C15 C17 C18 C20 C21 C22 C23 C24 C25 C26 C27 C28 C30 C32 C33 C34 C35 C36 C39 C42 C43 C44 C46 C48 C49 C50 C51 C52 C53 C60 C61 C74 C75 C76 C101 C102 C103 C104 C105 C114 C115 C116 C117 C118: library part C0603C104K5RACTU, "CAP CER 0.1UF 50V 10% X7R 0603"
C6 C29 C31 C37 C38 C40 C41 C45 C47 C62 C63 C64 C65: "CAP TANT 100UF 10V 10% 2917"
C9: library part C1608X5R1H105K080AB, "CAP CER 1UF 50V 10% X5R 0603"
C10 C54 C55 C56 C112 C113: "CAP CER 1UF 50V 10% X5R 0603"
C16 C19: "CAP TANT 330UF 10V 20% 2917"
C122 C125: "CAP CER 22PF 50V 5% NP0 0603"
C123 C124: "CAP CER 10PF 50V NP0 0603"
D1 D4: library part VS-10BQ030TRPBF, "DIODE SCHOTTKY 30V 1A DO214AA"
D2 D3 D7: library part VS-30BQ040TRPBF, "DIODE SCHOTTKY 40V 3A SMC"
D8: "DIODE SCHOTTKY 100V 1A DO214AA"
D9 D10 D11 D12: library part CZRF52C12, "DIODE ZENER 12V 200MW 1005"
FS1: library part 0157003.DR, "FUSE FAST 125VAC, 125VDC 3A SMD"
FS2 FS3 FS4 FS5 FS6: library part 0157001.DR, "FUSE FAST 125VAC, 125VDC 1A SMD"
J1 J4: "CONN HEADER 11POS .100 VERT GOLD"
J2: "CONN HEADER 6POS .100 VERT GOLD"
J3: "CONN HEADER 5POS .100 VERT GOLD"
J5 J13: "CONN HEADER 7POS .100 VERT GOLD"
J6: "CONN BNC JACK R/A 50 OHM PCB"
J7 J8: "CONN HEADER 4POS .100 VERT GOLD"
J9 J15 J16 J23: "CONN HEADER 3POS .100 VERT GOLD"
J10 J12 J14 J17 J18 J19 J20 J21: "CONN HEADER 2POS .100 VERT GOLD"
J11: "CONN HEADER 10POS VERT 10GOLD"
J22: "CONN HEADER 20POS VERT 10GOLD"
J88: "CONN EJECT MICROSD PUSH-PUSH SMD"
JU1 JU2 JU3 JU4 JU5 JU7 JU8: "BERGSTIK II .100\" SR STRAIGHT"
L1: "COIL PWR CHOKE 100UH 1A SMD"
Q1 Q3 Q5 Q7 Q9 Q11 Q13: "MOSFET N-CH 60V 150MA SOT23-3"
Q2: "TRANSISTOR NPN GP 40V SOT23"
Q4 Q6 Q8 Q10 Q12 Q14: library part IRFL9014TRPBF, "MOSFET P-CH 60V 1.8A SOT223"
R1 R56 R59 R62 R63: "RES 2K OHM 1/8W 5% 0805 SMD"
R2 R3 R12 R33 R34 R46: "RES 10 OHM 1/8W 5% 0805 SMD"
R4 R18 R35 R37 R38 R39 R40 R41 R47 R48 R49 R50 R55: "RES 100K OHM 1/8W 5% 0805 SMD"
R5 R7 R10 R11 R19 R20 R22 R25 R26 R28 R29 R30 R31 R32 R42 R44 R54: "RES 1M OHM 1/8W 5% 0805 SMD"
R6: "RES 1M OHM 1/8W 1% 0805 SMD"
R8: "RES 220 OHM 1/8W 5% 0805 SMD"
R9: "TRIMMER 1M OHM 0.25W SMD"
R13 R27: "RES 100K OHM 1/8W 1% 0805 SMD"
R14: library part ERJ-6ENF1004V, "RES 1.00M OHM 1/8W 1% 0805 SMD"
R15 R16 R21 R23 R24 R45 R51 R58: "RES 10K OHM 1/8W 5% 0805 SMD"
R17 R53: "RES 47 OHM 1/10W 5% 0603 SMD"
R36 R57: "RES 220K OHM 1/8W 5% 0805 SMD"
R43: "RES 20K OHM 1/8W 1% 0805 SMD"
R60 R61: "RES 330 OHM 1/8W 5% 0805 SMD"
SW3 SW4: "SWITCH TACTILE SPST-NO 0.05A 24V"
T1: "XFRMR 5V IN/OUT MAX 253 DIP"
TP1 TP2: library part 5006, "TEST POINT PC COMPACT .063\"D BLK"
U1 U2 U28: "OPTOCOUPLER DARL 5KVRMS 4SMD"
U3 U7: library part ADS1248IPW, "IC ADC 24BIT DEL/SIG LN 28TSSOP"
U4: "IC OSC MONO TIMING 3MHZ 8-SOIC"
U5: "IC REG BUCK BST INV 5V .4A 8SOIC"
U6 U8 U11 U14 U29: "OPTOCOUPLER 3.3V 8-SOIC"
U9: "Gate Drivers Transformer Driver for Iso RS-485 Int"
U10 U24: library part TPS79225DBVT, "IC REG LDO 2.5V 0.1A SOT23-5"
U12 U13 U18: "IC REG MULTI CONFIG ADJ 8-SOIC"
U15 U17: library part TPS3836L30DBVT, "IC 2.64V NANOPWR MON SOT-23-5"
U16: "IC TEMP SENSOR 2.7V SOT23-3"
U19: "IC OPAMP GP 75KHZ RRO 8SOIC"
U20 U23 U30: "IC DRVR/RCVR MULTCH RS232 20SOIC"
U21: "IC REG LDO ADJ 0.15A 8SOIC"
U22 U25 U26: "IC REG LDO 3.3V 0.15A 8SOIC"
U31: "IC MCU 32BIT 256KB FLASH 144LQFP"
X6: library part ABM3-16.000MHZ-D2Y-T, "CRYSTAL 16MHZ 18PF SMD"
X7: library part AB26TRB-32.768KHZ-T, "CRYSTAL 32.768KHZ 12.5PF THRU"

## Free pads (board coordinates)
  round 250 hole 150: 0(819,426) 1(819,3126) 2(7019,426) 3(7019,3126)

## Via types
v1: diameter 30, hole 15, Top Layer to Bottom Layer, 378 vias
v2: diameter 50, hole 25, Top Layer to Bottom Layer, 38 vias

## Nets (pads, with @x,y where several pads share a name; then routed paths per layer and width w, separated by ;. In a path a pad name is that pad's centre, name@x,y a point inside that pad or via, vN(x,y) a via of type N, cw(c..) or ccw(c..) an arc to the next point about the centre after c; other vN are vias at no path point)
+2.5V: C64.1 R34.2 U18.8 U24.5 | length 1533.9
  Top Layer w10: R34.2@4187.6,2425 4187.6,2467.6 4210,2490 v2(4305,2490)
  Top Layer w12: v1@4175,3074 4177,3072 U24.5@4212.6,3072 4212.6,3137.6 4275,3200 C64.1@4330.91,3200 4365,3200 4450,3285 4700,3285 4729.72,3255.28 U18.8@4729.72,3225
  Signal Layer 1 w12: v1@4175,3074 v1(4175,3075)
  Bottom Layer w10: v1(4175,3075) 4175,3074 4175,2915 4200,2890 4200,2595 v2(4305,2490)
